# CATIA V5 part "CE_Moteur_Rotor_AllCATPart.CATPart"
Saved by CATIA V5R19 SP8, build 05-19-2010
Part number: CE15_Moteur_Rotor_AllCATPart
Bounding box of the stored display mesh (mm): x 25.194 to 262.194, y 84.133 to 214.117, z 43.008 to 172.992
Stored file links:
  D:\Documents\1_Travail\1 - ac-limoges.fr\ac-limoges.fr\Emmanuel Maynard - STI2D_Turgot\2 -2I2D\1_SEQUENCE_ Tapis_de_course\3- Spécificités\Spé_ITEC\3-Pente\Tapis_TC520B_Pente\CE_Moteur_Rotor_AllCATPart.CATPart
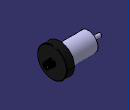
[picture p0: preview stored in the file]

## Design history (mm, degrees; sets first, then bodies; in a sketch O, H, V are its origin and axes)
AxisSystem1: origin (0, 0, 0), X (1, 0, 0), Y (0, 1, 0), Z (0, 0, 1)
Body1 (main body)
Body2 "Rotor.1\\Corps principal"
  Solid1: solid without history
Body3 "JIS B 1301 KEY 5x5x28 PARALLEL WITHOUT HOLES SYMBOL C.1\\PartBody"
  Solid2 "Solide.1": solid without history
Body4 "Poulie_inertie.1\\Corps principal"
  Solid3 "Solide.1": solid without history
